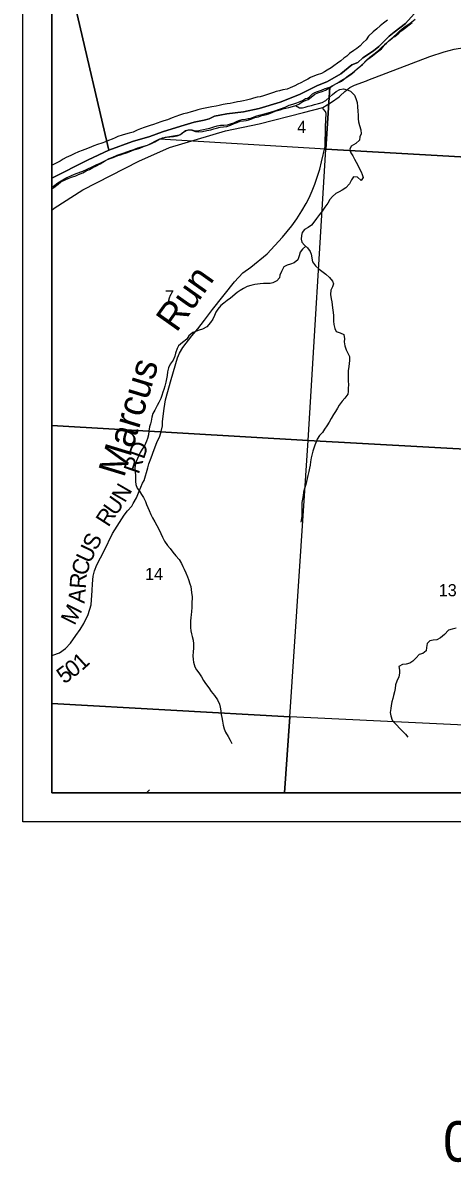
# Model space of a CAD drawing. Extents: x 0 to 34, y 0 to 22.
# Drawn here: x 23.917 to 25.404, y 12.821 to 16.768 of the extents above; entities that cross this region are included whole.
import ezdxf

# ---------------------------------------------------------------- set-up
doc = ezdxf.new("R2010")
doc.units = 0
for name, color, linetype in [('GM_X_County', 7, 'Continuous'), ('GM_X_County_Road', 7, 'Continuous'), ('GM_X_Major_River', 7, 'Continuous'), ('GM_X_Minor_River', 7, 'Continuous'), ('GM_X_Minor_River_Text', 7, 'Continuous'), ('GM_X_Section', 7, 'Continuous'), ('GM_X_Section_Text', 7, 'Continuous'), ('GM_X_Township', 7, 'Continuous'), ('GM_X_Township_Road', 7, 'Continuous'), ('GM_X_Township_Road_Text', 7, 'Continuous'), ('SH_Data', 7, 'Continuous'), ('SH_Text', 7, 'Continuous')]:
    doc.layers.add(name, color=color, linetype=linetype)

msp = doc.modelspace()

# ---------------------------------------------------------------- linework, layer by layer
at = {"layer": 'GM_X_County'}
msp.add_lwpolyline([(24.0167, 20.4902), (24.0167, 14.1), (30.8167, 14.1), (30.8167, 19.9966)], dxfattribs=at)
at = {"layer": 'GM_X_County_Road'}
for points in [[(25.1118, 16.5692), (25.327, 16.6512), (25.3767, 16.668), (25.4112, 16.6768), (25.4464, 16.6833), (25.4813, 16.6925), (25.5124, 16.7031), (25.5393, 16.7161), (25.5711, 16.7317), (25.5878, 16.7363), (25.6063, 16.7371), (25.6325, 16.7314), (25.6576, 16.7216), (25.6879, 16.7121), (25.7067, 16.7009), (25.7146, 16.6952), (25.7278, 16.6909), (25.7521, 16.6912), (25.8017, 16.7016), (25.8366, 16.7158), (25.8662, 16.7357), (25.8811, 16.7546), (25.8895, 16.7721)], [(25.0157, 16.5149), (25.0327, 16.5302), (25.0501, 16.5445), (25.0654, 16.5527), (25.1074, 16.5675), (25.1118, 16.5692)], [(24.0167, 16.1193), (24.0256, 16.1265), (24.1249, 16.1893), (24.3188, 16.2884), (24.4251, 16.3364), (24.6191, 16.3943), (24.7355, 16.4188), (24.8886, 16.4577), (24.9564, 16.4753), (24.9861, 16.4938), (25.0127, 16.5122), (25.0157, 16.5149)]]:
    msp.add_lwpolyline(points, dxfattribs=at)
at = {"layer": 'GM_X_Major_River'}
for points in [[(25.1796, 16.7774), (25.1667, 16.7673), (25.1544, 16.7583), (25.143, 16.7479), (25.13, 16.7366), (25.1139, 16.722), (25.1066, 16.7092), (25.0962, 16.7006), (25.0855, 16.689), (25.0737, 16.6797), (25.0637, 16.6726), (25.0485, 16.6618), (25.0389, 16.6532), (25.0293, 16.6453), (25.0179, 16.6367), (25.0064, 16.6285), (24.9946, 16.6196), (24.9847, 16.6125), (24.9713, 16.6039), (24.9618, 16.5987), (24.9515, 16.5932), (24.9363, 16.5884), (24.9268, 16.5851), (24.9135, 16.5792), (24.904, 16.5736), (24.8929, 16.5673), (24.88, 16.5607), (24.8697, 16.5558), (24.8587, 16.5495), (24.8434, 16.5425), (24.8321, 16.5389), (24.8176, 16.5356), (24.8062, 16.5327), (24.7949, 16.5302), (24.7854, 16.5273), (24.7747, 16.5236), (24.761, 16.5185), (24.7504, 16.5156), (24.7386, 16.5123), (24.7284, 16.5101), (24.7159, 16.5072), (24.7052, 16.5043), (24.6912, 16.5003), (24.6809, 16.4982), (24.67, 16.496), (24.6601, 16.4943), (24.6457, 16.4914), (24.6351, 16.4892), (24.6244, 16.4875), (24.6112, 16.485), (24.5975, 16.4821), (24.5865, 16.48), (24.5721, 16.4771), (24.5596, 16.475), (24.5482, 16.4725), (24.5372, 16.4703), (24.5235, 16.4663), (24.5129, 16.4638), (24.5004, 16.4597), (24.4844, 16.455), (24.4738, 16.4529), (24.4593, 16.4481), (24.4464, 16.4433), (24.4339, 16.4385), (24.4183, 16.4327), (24.4058, 16.4286), (24.3951, 16.425), (24.3826, 16.4202), (24.37, 16.4158), (24.3579, 16.4122), (24.348, 16.4092), (24.3366, 16.4052), (24.3244, 16.4008), (24.3127, 16.3968), (24.2993, 16.3897), (24.2849, 16.3857), (24.272, 16.3825), (24.2606, 16.3792), (24.2462, 16.3741), (24.2363, 16.3696), (24.2267, 16.3652), (24.2131, 16.36), (24.2036, 16.3556), (24.1906, 16.3512), (24.1754, 16.3465), (24.1633, 16.3424), (24.1469, 16.3354), (24.1317, 16.3299), (24.1218, 16.3262), (24.1093, 16.3207), (24.0952, 16.314), (24.083, 16.3085), (24.067, 16.3015), (24.0571, 16.2955), (24.0461, 16.2892), (24.0301, 16.2807), (24.019, 16.2751)], [(24.1361, 16.2552), (24.1475, 16.26), (24.1597, 16.267), (24.17, 16.2715), (24.1845, 16.28), (24.1997, 16.2889), (24.2096, 16.2949), (24.2199, 16.2985), (24.2294, 16.3022), (24.2454, 16.3081), (24.2552, 16.3114), (24.2647, 16.3143), (24.2765, 16.3183), (24.2914, 16.3239), (24.3016, 16.3279), (24.3111, 16.3308), (24.3221, 16.3341), (24.3347, 16.3393), (24.3484, 16.344), (24.3621, 16.3507), (24.3742, 16.3562), (24.3876, 16.3644), (24.4009, 16.3692), (24.4149, 16.3721), (24.4255, 16.3731), (24.4392, 16.3744), (24.4513, 16.3765), (24.4608, 16.3802), (24.4707, 16.3884), (24.4829, 16.3955), (24.4924, 16.3977), (24.5026, 16.396), (24.5154, 16.3913), (24.5264, 16.3901), (24.5397, 16.3914), (24.5541, 16.3947), (24.5677, 16.3979), (24.5787, 16.4008), (24.5882, 16.4037), (24.6, 16.4066), (24.6118, 16.4084), (24.6235, 16.4094), (24.6361, 16.4142), (24.649, 16.4193), (24.6589, 16.4234), (24.6695, 16.427), (24.6809, 16.4288), (24.6904, 16.4298), (24.6998, 16.4324), (24.7101, 16.436), (24.7207, 16.4397), (24.7337, 16.443), (24.7447, 16.4466), (24.7564, 16.4491), (24.7694, 16.4535), (24.783, 16.4591), (24.7941, 16.4631), (24.8077, 16.4671), (24.818, 16.4704), (24.8282, 16.4729), (24.8377, 16.4743), (24.851, 16.478), (24.862, 16.4816), (24.8734, 16.4864), (24.8833, 16.4928), (24.8929, 16.4983), (24.9058, 16.5027), (24.9153, 16.5106), (24.9287, 16.5207), (24.939, 16.5255), (24.9534, 16.5302), (24.9656, 16.5354), (24.9789, 16.5428), (24.9911, 16.551), (25.0052, 16.5588), (25.0201, 16.5681), (25.03, 16.574), (25.043, 16.5819), (25.0537, 16.5905), (25.0647, 16.5987), (25.0766, 16.6095), (25.0869, 16.6185), (25.1022, 16.6331), (25.1156, 16.6443), (25.1278, 16.654), (25.1454, 16.6678), (25.1588, 16.6787), (25.173, 16.6952), (25.1833, 16.7045), (25.1956, 16.715), (25.2055, 16.7213), (25.2188, 16.7326), (25.2292, 16.7412), (25.2437, 16.7524), (25.2548, 16.7613), (25.2655, 16.7692)], [(24.019, 16.2751), (24.0167, 16.274)], [(24.0167, 16.1931), (24.0242, 16.1978), (24.0391, 16.2097), (24.0486, 16.2168), (24.0631, 16.2242), (24.0737, 16.2286), (24.0859, 16.233), (24.1, 16.2382), (24.1099, 16.2426), (24.1243, 16.2489), (24.1361, 16.2552)]]:
    msp.add_lwpolyline(points, dxfattribs=at)
at = {"layer": 'GM_X_Minor_River'}
for points in [[(24.8616, 16.4815), (24.8754, 16.4732), (24.8857, 16.4742), (24.8952, 16.4763), (24.9051, 16.4791), (24.9172, 16.4819), (24.9271, 16.4848), (24.9416, 16.4883), (24.9537, 16.4926), (24.966, 16.4988), (24.9791, 16.5104), (24.9895, 16.52), (25.0025, 16.5304), (25.0152, 16.5374), (25.0273, 16.539), (25.0405, 16.5365), (25.0521, 16.531), (25.0659, 16.5178), (25.0709, 16.5056), (25.0748, 16.4919), (25.0765, 16.4778), (25.0777, 16.4615), (25.0782, 16.4497), (25.0787, 16.436), (25.08, 16.425), (25.0836, 16.4121), (25.0878, 16.3976), (25.0887, 16.3835), (25.084, 16.3734), (25.0826, 16.362), (25.0703, 16.3505), (25.0546, 16.3405), (25.0498, 16.3304), (25.053, 16.3174), (25.0596, 16.3078), (25.0658, 16.2959), (25.0713, 16.2852), (25.0776, 16.2752), (25.0815, 16.2645), (25.0885, 16.2519), (25.0925, 16.2423), (25.0957, 16.232), (25.089, 16.2219), (25.0756, 16.2339), (25.062, 16.2349), (25.055, 16.2245), (25.0483, 16.2105), (25.036, 16.1971), (25.0226, 16.1886), (25.013, 16.1828), (25.0008, 16.1765), (24.9896, 16.1661), (24.9807, 16.1561), (24.9736, 16.1429), (24.9631, 16.1291), (24.9542, 16.1156), (24.9441, 16.104), (24.9344, 16.0905), (24.9251, 16.0774), (24.9166, 16.0677), (24.9058, 16.0596), (24.8928, 16.0519), (24.8839, 16.0414), (24.8818, 16.0308), (24.8812, 16.0187), (24.8837, 16.0084), (24.8925, 15.998), (24.903, 15.9891), (24.9126, 15.9764), (24.9158, 15.9669), (24.9198, 15.9402), (24.9302, 15.9264), (24.9432, 15.9151), (24.9529, 15.9077), (24.966, 15.8973), (24.979, 15.8856), (24.989, 15.8737), (24.993, 15.8641), (24.9894, 15.854), (24.9838, 15.8423), (24.9828, 15.8275), (24.9848, 15.8123), (24.9869, 15.802), (24.9882, 15.791), (24.9895, 15.7811), (24.9922, 15.7651), (24.9931, 15.7538), (24.9928, 15.7344), (24.9944, 15.7226), (24.9976, 15.7089), (25.0027, 15.6993), (25.0162, 15.6941), (25.029, 15.6878), (25.0314, 15.6734), (25.0304, 15.6632), (25.0328, 15.6495), (25.0371, 15.6353), (25.0436, 15.6219), (25.048, 15.6124), (25.0485, 15.5983), (25.0471, 15.5877)], [(24.8968, 15.9944), (24.8855, 15.9837), (24.8773, 15.9733), (24.8737, 15.9604), (24.8696, 15.9476), (24.8573, 15.9372), (24.844, 15.9318), (24.8329, 15.9286), (24.8215, 15.9223), (24.8128, 15.9066), (24.8073, 15.8942), (24.806, 15.8843), (24.7967, 15.8739), (24.7826, 15.8673), (24.7731, 15.8652), (24.7602, 15.8651), (24.75, 15.8645), (24.7394, 15.8636), (24.7295, 15.8626), (24.72, 15.8617), (24.7067, 15.8585), (24.6934, 15.8542), (24.6808, 15.8476), (24.6693, 15.8406), (24.6597, 15.834), (24.6359, 15.8139), (24.6251, 15.8062), (24.6132, 15.7969), (24.6032, 15.7891), (24.592, 15.7764), (24.5858, 15.7659), (24.5806, 15.7547), (24.5747, 15.7411), (24.5673, 15.7299), (24.5538, 15.715), (24.5396, 15.7069), (24.5278, 15.7037), (24.5179, 15.7001), (24.5057, 15.6958), (24.4922, 15.6839), (24.4844, 15.6726), (24.4695, 15.6608), (24.4564, 15.6493), (24.4513, 15.6395), (24.4461, 15.6241), (24.4436, 15.6131), (24.4376, 15.5992), (24.4272, 15.5861), (24.4209, 15.5729), (24.4183, 15.559), (24.4166, 15.5465), (24.4145, 15.5351), (24.412, 15.5227), (24.4083, 15.5098), (24.4047, 15.4978), (24.4019, 15.488), (24.3979, 15.4774), (24.3943, 15.4669), (24.3879, 15.4526), (24.3824, 15.4424), (24.3742, 15.4266), (24.3672, 15.415), (24.3639, 15.4014), (24.3614, 15.3886), (24.3585, 15.3784), (24.3561, 15.3682), (24.3531, 15.3538), (24.3518, 15.3413), (24.3485, 15.3285), (24.3453, 15.3183), (24.3378, 15.3022), (24.33, 15.2909), (24.3234, 15.28), (24.317, 15.2665), (24.3103, 15.2511), (24.3059, 15.2383), (24.3052, 15.2224), (24.3062, 15.211), (24.3071, 15.2011), (24.3073, 15.1916), (24.3074, 15.1791), (24.3084, 15.1681), (24.3123, 15.1562), (24.3204, 15.1458), (24.3282, 15.1343), (24.3351, 15.1232), (24.3417, 15.1098), (24.3453, 15.0995), (24.35, 15.0884), (24.3544, 15.0784), (24.3602, 15.0647), (24.366, 15.0528), (24.3737, 15.039), (24.3806, 15.0267), (24.3876, 15.0137), (24.3945, 14.9992), (24.4007, 14.9858), (24.4076, 14.9724), (24.4183, 14.9578), (24.4276, 14.947), (24.436, 14.9339)], [(25.0471, 15.5877), (25.0458, 15.5775), (25.044, 15.5624), (25.0438, 15.5525), (25.044, 15.54), (25.0441, 15.5264), (25.0446, 15.5146), (25.044, 15.5009), (25.0438, 15.4911), (25.0421, 15.4813), (25.0324, 15.4674), (25.0231, 15.4577), (25.013, 15.4439), (25.0071, 15.4326), (25.0001, 15.4214), (24.9927, 15.4112), (24.9852, 15.397), (24.9778, 15.3846), (24.9704, 15.3715), (24.9622, 15.3599), (24.9544, 15.3486), (24.9444, 15.3389), (24.9362, 15.3262), (24.9326, 15.3164), (24.9282, 15.3047), (24.9254, 15.2945), (24.9218, 15.2844), (24.9181, 15.2708), (24.9153, 15.261), (24.9135, 15.247), (24.9118, 15.2353), (24.9097, 15.225), (24.9076, 15.2133), (24.9043, 15.2001), (24.9022, 15.1899), (24.899, 15.179), (24.8969, 15.1684), (24.8929, 15.1548), (24.8888, 15.142), (24.8879, 15.1306), (24.8853, 15.1178), (24.8836, 15.1068), (24.883, 15.0742), (24.8831, 15.0606), (24.8826, 15.0507), (24.8801, 15.0386)], [(24.436, 14.9339), (24.4468, 14.9216), (24.4579, 14.9092), (24.4667, 14.8946), (24.4714, 14.8847), (24.4758, 14.8748), (24.4812, 14.8621), (24.487, 14.8491), (24.4902, 14.8392), (24.4957, 14.8247), (24.4989, 14.8148), (24.5002, 14.8049), (24.5015, 14.7946), (24.5031, 14.7798), (24.5027, 14.7555), (24.502, 14.7426), (24.5014, 14.7286), (24.5001, 14.7176), (24.4991, 14.7074), (24.4977, 14.6953), (24.4971, 14.6836), (24.4973, 14.6737), (24.4986, 14.6615), (24.5011, 14.6516), (24.5032, 14.6421), (24.5063, 14.6288), (24.5076, 14.6166), (24.5077, 14.6014), (24.5063, 14.5893), (24.5057, 14.5753), (24.507, 14.5628), (24.5079, 14.5525), (24.5122, 14.5373), (24.5184, 14.5269), (24.5269, 14.5165), (24.5357, 14.5019), (24.5431, 14.4896), (24.5497, 14.4793), (24.5607, 14.4647), (24.5696, 14.4516), (24.5811, 14.4381), (24.5914, 14.4231), (24.5983, 14.4071), (24.6007, 14.3972), (24.6031, 14.3842), (24.6044, 14.3721), (24.6061, 14.3614), (24.6081, 14.3492), (24.6109, 14.3348), (24.6148, 14.3218), (24.6191, 14.3103), (24.6276, 14.2954), (24.6353, 14.2827), (24.6411, 14.2716)], [(25.4177, 14.6705), (25.4037, 14.6677), (25.3911, 14.6634), (25.3776, 14.6488), (25.3637, 14.6377), (25.3515, 14.6307), (25.3378, 14.6291), (25.3272, 14.6266), (25.3172, 14.6174), (25.3146, 14.6037), (25.3137, 14.5924), (25.3025, 14.5827), (25.29, 14.5799), (25.2792, 14.568), (25.2676, 14.5568), (25.2576, 14.5491), (25.2447, 14.5459), (25.2318, 14.5454), (25.2199, 14.5384), (25.222, 14.5258), (25.2218, 14.5148), (25.2193, 14.5027), (25.2125, 14.4873), (25.2074, 14.4749), (25.2068, 14.4624), (25.2043, 14.4503), (25.201, 14.4375), (25.1985, 14.4269), (25.1953, 14.4156), (25.1928, 14.4027), (25.1911, 14.3925), (25.1889, 14.3789), (25.1913, 14.3667), (25.1964, 14.3526), (25.2056, 14.3414), (25.229, 14.3171), (25.242, 14.3032), (25.2505, 14.2932)], [(24.3451, 14.1), (24.3554, 14.1109)]]:
    msp.add_lwpolyline(points, dxfattribs=at)
at = {"layer": 'GM_X_Section'}
for p, q in [((24.0167, 16.1977), (24.0167, 15.3726)), ((24.0167, 15.3726), (24.0167, 14.4099)), ((24.8234, 14.1), (25.8724, 14.1))]:
    msp.add_line(p, q, dxfattribs=at)
for points in [[(26.0152, 16.9679), (25.9802, 16.2732), (24.9665, 16.3307), (24.9804, 16.5448), (25.0031, 16.5575), (25.0207, 16.5664), (25.0339, 16.5765), (25.0442, 16.5841), (25.0586, 16.5954), (25.0754, 16.6093), (25.0929, 16.624), (25.1077, 16.6391), (25.1187, 16.6489), (25.1332, 16.6594), (25.1488, 16.6722), (25.1617, 16.6854), (25.1762, 16.6978), (25.1883, 16.708), (25.1978, 16.7163), (25.2169, 16.7348), (25.223, 16.7404), (25.237, 16.7517), (25.2583, 16.7675), (25.2762, 16.7807)], [(24.0167, 15.3726), (24.9048, 15.3211), (24.9665, 16.3307), (24.3905, 16.3649), (24.3472, 16.3429), (24.3146, 16.3334), (24.2998, 16.3282), (24.285, 16.3237), (24.2789, 16.3214), (24.2603, 16.3143), (24.2425, 16.308), (24.2273, 16.302), (24.2151, 16.2967), (24.2026, 16.29), (24.1836, 16.2814), (24.1696, 16.275), (24.1559, 16.2686), (24.1388, 16.2596), (24.124, 16.2529), (24.1005, 16.2446), (24.0842, 16.2383), (24.069, 16.2312), (24.0549, 16.2233), (24.0375, 16.2131), (24.028, 16.2045), (24.0207, 16.1996), (24.0167, 16.1977)], [(24.0167, 14.4099), (24.8423, 14.3642), (24.9048, 15.3211), (24.0167, 15.3726)], [(24.0167, 14.4099), (24.0167, 14.1), (24.8234, 14.1)], [(24.8234, 14.1), (24.8423, 14.3642), (24.0167, 14.4099)], [(25.8724, 14.1), (25.8818, 14.3145), (24.8423, 14.3642), (24.8234, 14.1)]]:
    msp.add_lwpolyline(points, dxfattribs=at)
for points in [[(24.9804, 16.5448), (24.9665, 16.3307), (24.3905, 16.3649), (24.4112, 16.3717), (24.4595, 16.3804), (24.4682, 16.3845), (24.4758, 16.3917), (24.4808, 16.3947), (24.4895, 16.397), (24.4982, 16.398), (24.502, 16.3976), (24.5092, 16.3953), (24.5167, 16.3938), (24.5217, 16.3938), (24.5312, 16.396), (24.5421, 16.3982), (24.5531, 16.4004), (24.5641, 16.4038), (24.5782, 16.4079), (24.5899, 16.4109), (24.6017, 16.4138), (24.6134, 16.4138), (24.6263, 16.4149), (24.6362, 16.4178), (24.6483, 16.4223), (24.6597, 16.4272), (24.6688, 16.4309), (24.6764, 16.4328), (24.6878, 16.435), (24.6976, 16.4365), (24.7033, 16.4372), (24.712, 16.4402), (24.7242, 16.4447), (24.736, 16.448), (24.7488, 16.4514), (24.7667, 16.4562), (24.7864, 16.4626), (24.8065, 16.4689), (24.8251, 16.4764), (24.8395, 16.4824), (24.8517, 16.4865), (24.8623, 16.4899), (24.8752, 16.4943), (24.8877, 16.5004), (24.8961, 16.506), (24.9033, 16.5071), (24.909, 16.5101), (24.9147, 16.5169), (24.9204, 16.5218), (24.928, 16.5267), (24.9375, 16.53), (24.9514, 16.5344), (24.9646, 16.5403)], [(25.9802, 16.2732), (25.9296, 15.2643), (24.9048, 15.3211), (24.9665, 16.3307)], [(25.9296, 15.2643), (25.8818, 14.3145), (24.8423, 14.3642), (24.9048, 15.3211)]]:
    msp.add_lwpolyline(points, close=True, dxfattribs=at)
at = {"layer": 'GM_X_Township'}
msp.add_line((24.0167, 17.2008), (24.0167, 16.2296), dxfattribs=at)
for points in [[(24.0167, 16.2296), (24.1434, 16.2932), (24.2144, 16.3267), (24.0999, 16.8163), (24.0167, 17.2008)], [(25.2825, 16.8107), (25.243, 16.7662), (25.2034, 16.7364), (25.1858, 16.7217), (25.1499, 16.6863), (25.1312, 16.6716), (25.0946, 16.6464), (25.0774, 16.6309), (25.0569, 16.6223), (25.0187, 16.591), (24.9726, 16.5647), (24.9349, 16.5494), (24.8748, 16.5194), (24.8086, 16.4932), (24.7352, 16.4717), (24.6808, 16.4595), (24.6238, 16.453), (24.5991, 16.4486), (24.5813, 16.4445), (24.5619, 16.4359), (24.5447, 16.4311), (24.5102, 16.4237), (24.4645, 16.4107), (24.401, 16.3903), (24.3569, 16.3742), (24.2968, 16.3571), (24.2144, 16.3267), (24.1434, 16.2932), (24.0167, 16.2296)], [(24.0999, 16.8163), (24.2144, 16.3267), (24.2968, 16.3571), (24.3569, 16.3742), (24.401, 16.3903), (24.4645, 16.4107), (24.5102, 16.4237), (24.5447, 16.4311), (24.5619, 16.4359), (24.5813, 16.4445), (24.5991, 16.4486), (24.6238, 16.453), (24.6808, 16.4595), (24.7352, 16.4717), (24.8086, 16.4932), (24.8748, 16.5194), (24.9349, 16.5494), (24.9726, 16.5647), (25.0187, 16.591), (25.0569, 16.6223), (25.0774, 16.6309), (25.0946, 16.6464), (25.1312, 16.6716), (25.1499, 16.6863), (25.1858, 16.7217), (25.2034, 16.7364), (25.243, 16.7662), (25.2825, 16.8107)], [(24.0167, 16.2296), (24.0167, 14.1), (25.8726, 14.1)]]:
    msp.add_lwpolyline(points, dxfattribs=at)
at = {"layer": 'GM_X_Township_Road'}
for points in [[(24.9658, 16.4095), (24.9672, 16.4539), (24.9652, 16.4605), (24.9576, 16.4707), (24.9564, 16.4753)], [(24.0167, 14.5762), (24.021, 14.5778), (24.0434, 14.5851), (24.0651, 14.6005), (24.0818, 14.6188), (24.1009, 14.6451), (24.1155, 14.6663), (24.1284, 14.6872), (24.143, 14.7185), (24.1531, 14.7512), (24.1575, 14.8018), (24.1582, 14.8249), (24.1606, 14.8511), (24.1656, 14.8696), (24.1731, 14.8904), (24.1989, 14.9391), (24.2275, 14.9993), (24.2681, 15.0624), (24.2791, 15.077), (24.2943, 15.094), (24.2985, 15.1031), (24.31, 15.1219), (24.3198, 15.1456), (24.3317, 15.1731), (24.3368, 15.1821), (24.3494, 15.2259), (24.3536, 15.24), (24.3619, 15.2616), (24.3713, 15.2897), (24.3811, 15.3144), (24.391, 15.3365), (24.3962, 15.3524), (24.4011, 15.3715), (24.4011, 15.387), (24.406, 15.4315), (24.411, 15.4616), (24.4308, 15.533), (24.4531, 15.6078), (24.4599, 15.6234), (24.4713, 15.6431), (24.5023, 15.6838), (24.5231, 15.7078), (24.5466, 15.7382), (24.5738, 15.7747), (24.6502, 15.8712), (24.6794, 15.9021), (24.707, 15.9222), (24.7628, 15.9675), (24.8165, 16.0257), (24.849, 16.0653), (24.866, 16.0888), (24.8831, 16.117), (24.8978, 16.1417), (24.9088, 16.1622), (24.919, 16.1865), (24.9284, 16.2097), (24.9452, 16.2615), (24.9518, 16.2865), (24.9636, 16.3393), (24.9658, 16.4095)]]:
    msp.add_lwpolyline(points, dxfattribs=at)
at = {"layer": 'SH_Data'}
for points in [[(23.9167, 21), (30.9167, 21), (30.9167, 14), (23.9167, 14)], [(24.0167, 20.9), (30.8167, 20.9), (30.8167, 14.1), (24.0167, 14.1)]]:
    msp.add_lwpolyline(points, close=True, dxfattribs=at)

# ---------------------------------------------------------------- texts
at = {"layer": 'GM_X_Minor_River_Text'}
for s, height, rotation, p in [('Run', 0.0947, 54.7033, (24.4491, 15.6926)), ('Marcus', 0.09471, 73.094, (24.2674, 15.1899))]:
    msp.add_text(s, height=height, rotation=rotation, dxfattribs=at).set_placement(p)
at = {"layer": 'GM_X_Section_Text'}
for s, height, p in [('4', 0.0419, (24.8672, 16.3868)), ('7', 0.0419, (24.4093, 15.7995)), ('14', 0.04186, (24.3401, 14.8376)), ('13', 0.04186, (25.3576, 14.7815))]:
    msp.add_text(s, height=height, rotation=0, dxfattribs=at).set_placement(p)
at = {"layer": 'GM_X_Township_Road_Text'}
for s, height, rotation, p in [('RD', 0.05682, 70.8032, (24.3178, 15.2022)), ('N', 0.0568, 59.9399, (24.2704, 15.1027)), ('U', 0.0568, 54.5254, (24.2382, 15.0572)), ('R', 0.0568, 57.2702, (24.2134, 15.0185)), ('S', 0.0568, 63.4498, (24.1713, 14.9371)), ('U', 0.0568, 64.445, (24.1498, 14.8922)), ('C', 0.0568, 73.9442, (24.1378, 14.8497)), ('R', 0.0568, 85.8389, (24.135, 14.8062)), ('A', 0.0568, 84.7402, (24.1303, 14.7552)), ('M', 0.0568, 63.2804, (24.0962, 14.6779)), ('1', 0.0568, 42.3916, (24.1216, 14.5215)), ('5', 0.0568, 36.2592, (24.0603, 14.4755)), ('0', 0.0568, 37.0131, (24.0891, 14.4967))]:
    msp.add_text(s, height=height, rotation=rotation, dxfattribs=at).set_placement(p)
at = {"layer": 'SH_Text'}
msp.add_text('0', height=0.14, dxfattribs=at).set_placement((25.3726, 12.8225))

doc.saveas('drawing.dxf')
